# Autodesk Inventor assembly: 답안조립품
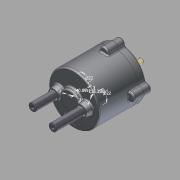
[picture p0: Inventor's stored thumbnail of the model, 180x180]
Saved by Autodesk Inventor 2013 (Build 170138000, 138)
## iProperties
Created: 2015-02
Part Number: 답안조립품
Document SubType Name: Assembly
Designer: Administrator
Author: Administrator
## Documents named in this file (13)
- C:\Users\Administrator\Desktop\350208V1015\답안조립품.iam
- C:\Users\Administrator\Desktop\350208V1015\몸체.ipt
- C:\Users\Administrator\Desktop\350208V1015\메인 축.ipt
- C:\Users\Administrator\Desktop\350208V1015\베어링 NA 4900.ipt
- C:\Users\Administrator\Desktop\350208V1015\멈춤링 10 x 1.ipt
- C:\Users\Administrator\Desktop\350208V1015\판캠.ipt
- C:\Users\Administrator\Desktop\350208V1015\멈춤링 22 x 1.2.ipt
- C:\Users\Administrator\Desktop\350208V1015\커버.ipt
- C:\Users\Administrator\Desktop\350208V1015\오일실.ipt
- C:\Users\Administrator\Desktop\350208V1015\M5x0.5x20.ipt
- C:\Users\Administrator\Desktop\350208V1015\슬라이드 축.ipt
- C:\Users\Administrator\Desktop\350208V1015\가변스프링1.ipt
- C:\Users\Administrator\Desktop\350208V1015\가변스프링2.ipt
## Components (6 placed, 3 different names)
1. M5x0.5x20:1
2. M5x0.5x20:2
3. M5x0.5x20:3
4. M5x0.5x20:4
5. 가변스프링1:1
6. 가변스프링2:1
